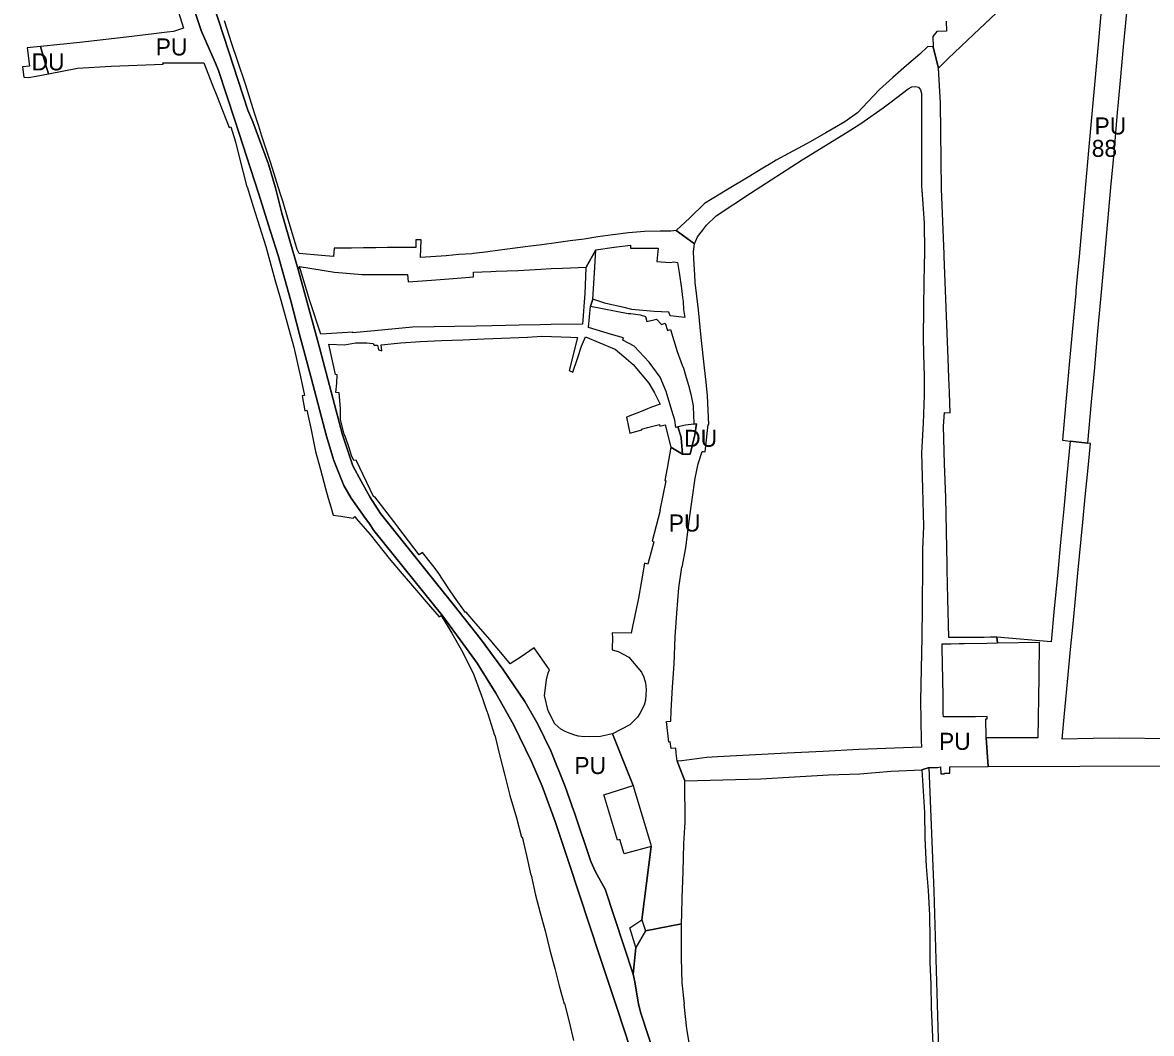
# Model space of a CAD drawing. Extents: x -521047 to -518054, y -1194945 to -1189555.
# Drawn here: x -520301 to -519638, y -1191621 to -1191028 of the extents above; entities that cross this region are included whole.
import ezdxf

# ---------------------------------------------------------------- set-up
doc = ezdxf.new("R2010")
doc.units = 0
for name, color, linetype in [('90310013', 7, 'Continuous'), ('90320013', 7, 'Continuous'), ('90450013', 7, 'Continuous'), ('90450023', 7, 'Continuous'), ('ID_navrh', 7, 'Continuous')]:
    doc.layers.add(name, color=color, linetype=linetype)

msp = doc.modelspace()

# ---------------------------------------------------------------- linework, layer by layer
at = {"layer": '90310013'}
for points in [[(-520290.15, -1191041.66), (-520297.9, -1191042.46), (-520296.62, -1191053.24), (-520300.69, -1191053.74), (-520299.9, -1191059.72), (-520297.2, -1191059.84), (-520292.62, -1191059.21), (-520285.55, -1191057.83), (-520287.18, -1191052.09), (-520290.15, -1191041.66)], [(-519916.16, -1191265), (-519914.43, -1191270.35), (-519914.24, -1191271.29), (-519913.38, -1191280.91), (-519908.95, -1191281.05), (-519906.08, -1191269.66), (-519905.16, -1191263.23), (-519906.65, -1191263.39), (-519911.61, -1191263.94), (-519916.16, -1191265)]]:
    msp.add_lwpolyline(points, dxfattribs=at)
at = {"layer": '90320013'}
for points in [[(-519929.33, -1191635.28), (-519937.84, -1191609.04), (-519939.31, -1191603.72), (-519941.34, -1191590.66), (-519942.38, -1191586.04), (-519958.85, -1191536.25), (-519964.41, -1191526.07), (-519967.28, -1191520.06), (-519976.95, -1191490.92), (-519977.14, -1191490.38), (-519982.28, -1191475.94), (-519990.75, -1191455.16), (-519998.32, -1191439.49), (-520005.92, -1191426.11), (-520018.78, -1191407.14), (-520031.96, -1191389.34), (-520047.36, -1191369.85), (-520056.18, -1191358.82), (-520087.5, -1191319.73), (-520090.59, -1191315.75), (-520096.97, -1191306.04), (-520102.06, -1191296.87), (-520106.82, -1191287.91), (-520108.84, -1191282.02), (-520112.91, -1191269.59), (-520126.29, -1191219.24), (-520128.27, -1191211.94), (-520139.04, -1191172.67), (-520142.39, -1191160.56), (-520148.63, -1191139.62), (-520152.18, -1191124.76), (-520156.39, -1191110.87), (-520165.49, -1191085.96), (-520168.55, -1191079.12), (-520182.63, -1191035.95), (-520230.16, -1190890.07)], [(-520204.26, -1191006.85), (-520195.92, -1191032.27), (-520192.65, -1191040.04), (-520187.45, -1191051.48), (-520185.72, -1191055.89), (-520176.15, -1191085.01), (-520162.23, -1191127.79), (-520155.09, -1191150.37), (-520150.78, -1191164.31), (-520143.35, -1191191.06), (-520138.27, -1191209.95), (-520131.25, -1191236.23), (-520122.24, -1191270.5), (-520118.08, -1191284.68), (-520112.12, -1191299.26), (-520107.85, -1191306.72), (-520099.92, -1191318.12), (-520097.08, -1191321.95), (-520094.55, -1191325.76), (-520054.11, -1191375.97), (-520040.12, -1191395.1), (-520033.82, -1191403.71), (-520022.9, -1191421.16), (-520012.56, -1191439.55), (-520001.92, -1191461.39), (-519995.8, -1191475.78), (-519988.12, -1191496.63), (-519987.95, -1191497.1), (-519979.96, -1191521.18), (-519962.02, -1191575.25), (-519951.7, -1191606.35), (-519940.4, -1191640.9)]]:
    msp.add_lwpolyline(points, dxfattribs=at)
at = {"layer": '90450013'}
for points in [[(-520230.16, -1190890.07), (-520182.63, -1191035.95), (-520168.55, -1191079.12), (-520165.49, -1191085.96), (-520156.39, -1191110.87), (-520152.18, -1191124.76), (-520148.63, -1191139.62), (-520142.39, -1191160.56), (-520139.04, -1191172.67), (-520138.13, -1191170.78), (-520117.56, -1191174.16), (-520101.36, -1191175.5), (-520098.41, -1191175.51), (-520085.69, -1191175.56), (-520074.77, -1191175.58), (-520074.38, -1191179.89), (-520060.7, -1191178.8), (-520048.06, -1191177.79), (-520035.98, -1191176.83), (-520036.11, -1191174.26), (-520025.87, -1191173.81), (-520022.83, -1191173.67), (-520009.79, -1191173.09), (-519996.61, -1191172.4), (-519990.39, -1191172.07), (-519983.74, -1191171.91), (-519970.02, -1191171.19), (-519964.25, -1191161.05), (-519953.43, -1191159.49), (-519943.95, -1191158.24), (-519943.98, -1191160.12), (-519935.85, -1191160.12), (-519927.72, -1191160.13), (-519928.53, -1191167.88), (-519920.55, -1191168.51), (-519918.44, -1191168.12), (-519916.29, -1191168.48), (-519915.26, -1191174.39), (-519913.96, -1191183.78), (-519913.39, -1191189.06), (-519913, -1191191.33), (-519912.75, -1191196.14), (-519912.03, -1191200.85), (-519920.68, -1191199.83), (-519921.43, -1191197.69), (-519929.98, -1191197.2), (-519943.03, -1191196), (-519947.61, -1191194.92), (-519958.38, -1191192.52), (-519966.04, -1191190.04), (-519967.41, -1191194.21), (-519945.24, -1191198.35), (-519943.8, -1191198.34), (-519938.16, -1191199.21), (-519935.07, -1191200.13), (-519934.36, -1191203.1), (-519928.62, -1191201.78), (-519925.65, -1191204.83), (-519923.55, -1191204.18), (-519922.15, -1191208.43), (-519920.47, -1191207.87), (-519916.57, -1191220.78), (-519913.59, -1191228.72), (-519912.89, -1191230.58), (-519911.2, -1191236.06), (-519909.81, -1191240.56), (-519908.47, -1191245.74), (-519907.22, -1191252.6), (-519906.89, -1191258.42), (-519906.67, -1191262.43), (-519906.65, -1191263.39), (-519905.16, -1191263.23), (-519906.08, -1191269.66), (-519908.95, -1191281.05), (-519913.38, -1191280.91), (-519920.21, -1191276.92), (-519922.38, -1191289.15), (-519923.7, -1191296.5), (-519923.11, -1191296.61), (-519926.79, -1191313.93), (-519926.46, -1191314.06), (-519931.24, -1191332.12), (-519930.12, -1191332.44), (-519933.8, -1191345.5), (-519935.76, -1191344.99), (-519937.5, -1191355.37), (-519939.28, -1191365.4), (-519942.75, -1191382.18), (-519943.6, -1191386.09), (-519954.59, -1191385.78), (-519954.39, -1191389.04), (-519954.6, -1191395.07), (-519954.76, -1191395.73), (-519951.1, -1191396.7), (-519944.83, -1191400.03), (-519937.5, -1191408.96), (-519936.08, -1191411.87), (-519935.13, -1191415.1), (-519934.72, -1191419.07), (-519935.15, -1191425.43), (-519935.94, -1191428.27), (-519938.47, -1191433.25), (-519939.86, -1191435.3), (-519944.28, -1191439.79), (-519954.39, -1191445.09), (-519942.41, -1191475.46), (-519941.97, -1191476.92), (-519932.24, -1191509.41), (-519931.7, -1191511.23), (-519937.21, -1191554.24), (-519935.12, -1191560.62), (-519913.95, -1191556.52), (-519913.95, -1191556.32), (-519913.77, -1191550.69), (-519913.55, -1191541.51), (-519913.02, -1191525.99), (-519912.6, -1191509.42), (-519912.08, -1191500.02), (-519911.87, -1191497.15), (-519912.09, -1191472.75), (-519916.57, -1191461.19), (-519917.06, -1191456.51), (-519917.37, -1191453.48), (-519920.04, -1191453.76), (-519920.61, -1191449.84), (-519921.5, -1191449.97), (-519922.75, -1191437.85), (-519920.31, -1191437.6), (-519920.06, -1191431.33)], [(-519940.4, -1191640.9), (-519951.7, -1191606.35), (-519962.02, -1191575.25), (-519979.96, -1191521.18), (-519987.95, -1191497.1), (-519988.12, -1191496.63), (-519995.8, -1191475.78), (-520001.92, -1191461.39), (-520012.56, -1191439.55), (-520022.9, -1191421.16), (-520033.82, -1191403.71), (-520040.12, -1191395.1), (-520054.11, -1191375.97), (-520094.55, -1191325.76), (-520097.08, -1191321.95), (-520099.92, -1191318.12), (-520107.85, -1191306.72), (-520112.12, -1191299.26), (-520118.08, -1191284.68), (-520122.24, -1191270.5), (-520131.25, -1191236.23), (-520138.27, -1191209.95), (-520143.35, -1191191.06), (-520150.78, -1191164.31), (-520155.09, -1191150.37), (-520162.23, -1191127.79), (-520176.15, -1191085.01), (-520185.72, -1191055.89), (-520187.45, -1191051.48), (-520192.65, -1191040.04), (-520195.92, -1191032.27), (-520204.26, -1191006.85)], [(-520210.43, -1191017.92), (-520206.21, -1191031.01), (-520212.09, -1191033), (-520215.8, -1191033.39), (-520222.04, -1191034.03), (-520236.52, -1191035.95), (-520267.13, -1191039.3), (-520290.15, -1191041.66)], [(-519758.73, -1191026.94), (-519758.39, -1191032.67), (-519764.15, -1191032.99), (-519766.57, -1191035.82), (-519766.2, -1191042.12), (-519763.15, -1191054.45), (-519757.4, -1191048.8), (-519742.58, -1191034.77), (-519725.84, -1191018.93)], [(-519920.06, -1191431.33), (-519919.21, -1191417.69), (-519918.28, -1191404.11), (-519917.62, -1191388.13), (-519916.71, -1191374.33), (-519915.54, -1191359.47), (-519913.79, -1191347.3), (-519913.62, -1191347.33), (-519911.48, -1191335.89), (-519909.39, -1191320.12), (-519905.88, -1191295.06), (-519904.2, -1191286.61), (-519901.8, -1191279.37), (-519901.12, -1191279.43), (-519900.01, -1191279.6), (-519898.29, -1191263.61), (-519897.85, -1191263.62), (-519898.78, -1191246.64), (-519899.59, -1191238.79), (-519900.46, -1191230.4), (-519902.53, -1191212.53), (-519904.01, -1191196.27), (-519905.9, -1191180.16), (-519906.15, -1191175.73), (-519906.66, -1191166.6), (-519906.92, -1191162.01), (-519906.3, -1191157.45), (-519917.19, -1191149.74), (-519920.32, -1191150.09), (-519926.43, -1191150.12), (-519935.74, -1191150.21), (-519945.04, -1191151.11), (-519954.19, -1191152.2), (-519963.01, -1191153.4), (-519971.18, -1191154.8), (-519979.27, -1191155.87), (-519987.57, -1191156.97), (-519995.89, -1191158.07), (-520004.25, -1191159.18), (-520020.52, -1191161.34), (-520029.05, -1191162.47), (-520035.97, -1191163.26), (-520036.96, -1191163.37), (-520044.63, -1191163.89), (-520052.03, -1191164.58), (-520067.15, -1191165.61), (-520066.74, -1191155.17), (-520069.93, -1191155.16), (-520069.95, -1191159.63), (-520079.48, -1191159.67), (-520086.45, -1191159.75), (-520093.39, -1191159.83), (-520100.51, -1191159.91), (-520107.64, -1191159.99), (-520117.85, -1191160.11), (-520118.2, -1191164.94), (-520125.16, -1191164.31), (-520138.44, -1191163.28), (-520139.59, -1191160.92), (-520145.2, -1191141.87), (-520147.8, -1191133.04), (-520149.55, -1191127.71), (-520154.98, -1191110.13), (-520160.34, -1191094.39), (-520162.03, -1191088.51), (-520164.64, -1191080.79), (-520169.68, -1191064.45), (-520174.58, -1191049.98), (-520177.92, -1191040.13), (-520182.12, -1191026.63)], [(-520290.15, -1191041.66), (-520287.18, -1191052.09), (-520285.55, -1191057.83), (-520268.52, -1191054.51), (-520248.67, -1191053.28), (-520218.2, -1191052.16), (-520218.34, -1191051.28), (-520194.34, -1191051.32), (-520193.93, -1191052.35), (-520189.56, -1191063.43), (-520186.26, -1191071.67), (-520182.97, -1191080.18), (-520179.53, -1191089.2), (-520178.54, -1191088.91), (-520175.78, -1191097.65), (-520173.5, -1191106.5), (-520169.07, -1191124.06), (-520168.8, -1191124), (-520165.31, -1191135.53), (-520161.55, -1191147.43), (-520157.86, -1191159.19), (-520152.57, -1191178.38), (-520149.52, -1191189.15), (-520147.14, -1191197.72), (-520144.34, -1191207.7), (-520141.5, -1191218.1), (-520137.26, -1191237.41), (-520135.23, -1191246.57), (-520136.61, -1191246.77), (-520135.11, -1191255.48), (-520133.8, -1191255.22), (-520131.57, -1191265.71), (-520128.76, -1191279.31), (-520125.9, -1191289.88), (-520122.99, -1191301.11), (-520121.28, -1191306.84), (-520119.8, -1191311.78), (-520118.33, -1191316.72), (-520113.9, -1191317.42), (-520106.74, -1191318.55), (-520105.72, -1191317.64), (-520104.86, -1191318.64), (-520096.75, -1191328.08), (-520085.55, -1191342.11), (-520077.83, -1191351.1), (-520070.7, -1191359.65), (-520063.86, -1191367.71), (-520056.23, -1191376.45), (-520055.09, -1191375.72), (-520048.83, -1191385.95), (-520043.17, -1191395.94), (-520039.57, -1191402.87), (-520035.85, -1191410.48), (-520030.86, -1191424.4), (-520028.75, -1191430.16), (-520027.59, -1191433.32), (-520023.82, -1191445.95), (-520023.55, -1191445.91), (-520020.73, -1191457.45), (-520017.66, -1191469.57), (-520014.7, -1191481.23), (-520010.89, -1191494.47), (-520010.73, -1191494.41), (-520007.79, -1191505.69), (-520007.55, -1191505.56), (-520004.99, -1191516.5), (-520002.46, -1191528.07), (-520002.17, -1191528.01), (-519999.67, -1191539.74), (-519997.02, -1191550.13), (-519996.86, -1191550.12), (-519994.03, -1191560.71), (-519991.17, -1191572.07), (-519988.4, -1191582.72), (-519985.82, -1191593.01), (-519982.81, -1191603.46), (-519982.61, -1191603.4), (-519979.91, -1191614.16), (-519977.29, -1191625.06)], [(-519756.23, -1191256.68), (-519756.69, -1191244.83), (-519757.02, -1191236.26), (-519757.46, -1191224.85), (-519758.24, -1191204.87), (-519759.79, -1191165), (-519759.85, -1191163.64), (-519761.34, -1191125.25), (-519762.07, -1191075.06), (-519763.15, -1191054.45), (-519766.2, -1191042.12), (-519766.5, -1191042.12), (-519766.53, -1191041.7), (-519769.56, -1191041.92), (-519774.17, -1191046.21), (-519781.93, -1191052.87), (-519789.9, -1191059.99), (-519797.75, -1191067), (-519804.69, -1191074.24), (-519810.75, -1191080.57), (-519818.12, -1191085.97), (-519829.31, -1191092.4), (-519838.45, -1191097.64), (-519840.61, -1191098.81), (-519851.15, -1191104.5), (-519858.51, -1191108.47), (-519862.58, -1191110.94), (-519866.19, -1191113.13), (-519874.86, -1191118.39), (-519886.98, -1191125.74), (-519900.42, -1191133.89), (-519909.06, -1191142.26), (-519917.19, -1191149.74), (-519906.3, -1191157.45), (-519904.56, -1191153.47), (-519901.59, -1191149.65), (-519899.24, -1191146.62), (-519893.57, -1191141.01), (-519873.58, -1191127.87), (-519843.17, -1191108.24), (-519816.71, -1191092.03), (-519808.76, -1191086.91), (-519795.57, -1191077.78), (-519790.92, -1191074.25), (-519780.88, -1191066.51), (-519778.77, -1191065.35), (-519776.49, -1191065.19), (-519774.92, -1191065.69), (-519773.63, -1191067.16), (-519773.09, -1191069.29), (-519773.08, -1191073.94), (-519773.05, -1191092.19), (-519773.06, -1191101.44), (-519773.1, -1191123.95), (-519772.97, -1191125.9), (-519771.62, -1191145.39), (-519771.43, -1191162.03), (-519771.76, -1191179.56), (-519771.96, -1191195.31), (-519772.12, -1191213.02), (-519771.84, -1191229.67), (-519771.55, -1191234.29), (-519771.54, -1191246.41), (-519772.05, -1191262.81), (-519773.13, -1191280.12), (-519772.53, -1191301.2), (-519772, -1191323.45), (-519772.56, -1191336.73), (-519772.53, -1191348.9), (-519772.74, -1191367.61), (-519772.78, -1191370.92), (-519772.98, -1191388.27), (-519773.78, -1191425.6), (-519773.27, -1191448.99), (-519773.21, -1191452.93), (-519809.91, -1191454.37), (-519830.9, -1191455.42), (-519851.93, -1191456.47), (-519892.88, -1191458.5), (-519899.19, -1191459.03), (-519913.72, -1191460.84), (-519916.57, -1191461.19), (-519912.09, -1191472.75), (-519867.51, -1191471.49), (-519847.68, -1191470.41), (-519827.66, -1191469.23), (-519809.38, -1191468.51), (-519791.02, -1191466.98), (-519772.94, -1191466.17), (-519768.59, -1191464.89), (-519763.77, -1191464.94), (-519761.94, -1191464.39), (-519761.87, -1191468.64), (-519759.57, -1191468.66), (-519759.58, -1191468.17), (-519756.5, -1191468.24), (-519756.52, -1191464.38), (-519734.08, -1191464.3), (-519735.24, -1191447.53), (-519735.35, -1191436.29), (-519734.64, -1191436.32), (-519734.65, -1191434.99), (-519741.34, -1191435.03), (-519750.83, -1191435.08), (-519760.31, -1191435.14), (-519760.35, -1191433.14), (-519760.41, -1191429.18), (-519760.5, -1191422.78), (-519760.92, -1191394.34), (-519760.94, -1191392.31), (-519760.93, -1191392.31), (-519755.94, -1191392.22), (-519750.95, -1191392.13), (-519748.1, -1191392.08), (-519734.6, -1191391.84), (-519728.58, -1191391.74), (-519728.83, -1191388.41), (-519732.63, -1191388.44), (-519736.35, -1191388.47), (-519757.13, -1191388.64), (-519757.61, -1191365.82), (-519757.97, -1191348.75), (-519758.03, -1191345.99), (-519758.44, -1191326.19), (-519758.86, -1191306.37), (-519759.53, -1191286.62), (-519760.31, -1191264.48), (-519759.7, -1191256.5), (-519756.23, -1191256.68)], [(-519977.75, -1191232.89), (-519975.09, -1191224.78), (-519972.7, -1191217.51), (-519970.38, -1191212.1), (-519953.47, -1191219.12), (-519952.81, -1191219.41), (-519947.91, -1191223.59), (-519942.39, -1191228.3), (-519933.11, -1191239.36), (-519929.76, -1191245.02), (-519926.51, -1191251.7), (-519931.68, -1191253.32), (-519935.33, -1191254.97), (-519939.55, -1191256.63), (-519942.81, -1191257.91), (-519946.16, -1191259.22), (-519944.27, -1191268.71), (-519937.27, -1191266.67), (-519937.35, -1191266.3), (-519933.91, -1191265.26), (-519926.88, -1191263.59), (-519926.61, -1191264.58), (-519923.57, -1191263.81), (-519920.21, -1191276.92), (-519913.38, -1191280.91), (-519914.24, -1191271.29), (-519914.43, -1191270.35), (-519916.16, -1191265), (-519917.33, -1191265.27), (-519917.97, -1191260.92), (-519919.56, -1191255.43), (-519922.97, -1191244.2), (-519926.57, -1191235.7), (-519932.99, -1191226.94), (-519941.84, -1191217.63), (-519948.33, -1191214.01), (-519947.97, -1191212.68), (-519955.03, -1191210.72), (-519968.52, -1191206.69), (-519967.41, -1191194.21), (-519966.04, -1191190.04), (-519965.08, -1191174.59), (-519964.25, -1191161.05), (-519970.02, -1191171.19), (-519970.04, -1191171.59), (-519970.65, -1191186.76), (-519972.15, -1191204.62), (-519990.46, -1191204.97), (-519996.86, -1191205.09), (-520009.2, -1191205.33), (-520025.3, -1191205.64), (-520034.44, -1191205.82), (-520046.93, -1191206.05), (-520059.07, -1191206.28), (-520071.84, -1191206.53), (-520094.07, -1191208.67), (-520106.88, -1191209.86), (-520106.94, -1191209.29), (-520125.69, -1191210.45), (-520132.06, -1191191), (-520138.13, -1191170.78), (-520139.04, -1191172.67), (-520128.27, -1191211.94), (-520126.29, -1191219.24), (-520112.91, -1191269.59), (-520108.84, -1191282.02), (-520106.82, -1191287.91), (-520102.06, -1191296.87), (-520096.97, -1191306.04), (-520090.59, -1191315.75), (-520087.5, -1191319.73), (-520056.18, -1191358.82), (-520047.36, -1191369.85), (-520031.96, -1191389.34), (-520018.78, -1191407.14), (-520005.92, -1191426.11), (-519998.32, -1191439.49), (-519990.75, -1191455.16), (-519982.28, -1191475.94), (-519977.14, -1191490.38), (-519976.95, -1191490.92), (-519967.28, -1191520.06), (-519964.41, -1191526.07), (-519958.85, -1191536.25), (-519942.38, -1191586.04), (-519940.69, -1191570.43), (-519941.33, -1191568.45), (-519944.39, -1191558.98), (-519937.21, -1191554.24), (-519931.7, -1191511.23), (-519947.58, -1191515.44), (-519950.26, -1191507.13), (-519951.55, -1191507.52), (-519959.23, -1191482.01), (-519959.57, -1191480.86), (-519942.41, -1191475.46), (-519954.39, -1191445.09), (-519961.53, -1191446.75), (-519971.13, -1191446.91), (-519974.5, -1191446.39), (-519976.56, -1191445.88), (-519979.32, -1191444.93), (-519982.27, -1191443.78), (-519984.74, -1191442.4), (-519988.3, -1191439.28), (-519992.15, -1191431.52), (-519994.38, -1191422.52), (-519993.24, -1191413.37), (-519992.22, -1191409.33), (-519991.42, -1191407.59), (-520000.38, -1191394.59), (-520008.16, -1191399.97), (-520014.57, -1191404), (-520016.12, -1191402.07), (-520026.28, -1191389.97), (-520034.63, -1191380.32), (-520040.42, -1191373.62), (-520040.73, -1191373.84), (-520047.19, -1191364.83), (-520050.47, -1191359.95), (-520056.7, -1191350.51), (-520059.94, -1191346.32), (-520065.92, -1191338.59), (-520067.95, -1191340.12), (-520077.35, -1191327.73), (-520082.89, -1191320.43), (-520093.9, -1191305.93), (-520094.5, -1191306.24), (-520104.98, -1191284.57), (-520106.3, -1191284.7), (-520107.61, -1191281.7), (-520108.9, -1191277.92), (-520111.26, -1191271), (-520111.87, -1191269.22), (-520114.16, -1191260.56), (-520114.12, -1191254.11), (-520114.83, -1191244.91), (-520116.83, -1191244.69), (-520116.22, -1191239.35), (-520116.09, -1191234.37), (-520116.97, -1191234.24), (-520121.04, -1191216.51), (-520111.74, -1191216.83), (-520105.33, -1191215.65), (-520098.62, -1191215.71), (-520095.07, -1191216.04), (-520094.3, -1191217.09), (-520092.4, -1191216.95), (-520091.83, -1191219.76), (-520089.85, -1191220.37), (-520090.21, -1191216.78), (-520078.64, -1191215.7), (-520067.14, -1191214.8), (-520054.83, -1191214.31), (-520042.28, -1191213.81), (-520029.73, -1191213.31), (-520004.4, -1191212.3), (-519996.02, -1191211.66), (-519978.9, -1191212.24), (-519975.11, -1191212.49), (-519979.96, -1191231.95), (-519977.75, -1191232.89)], [(-519627.09, -1191448.06), (-519657.04, -1191447.59), (-519672.39, -1191447.84), (-519690.58, -1191448.2), (-519689.15, -1191433.2), (-519686.98, -1191410.48), (-519685.63, -1191395.51), (-519684.19, -1191380.58), (-519682.82, -1191365.8), (-519681.41, -1191350.72), (-519678.45, -1191320.85), (-519677.01, -1191305.92), (-519675.58, -1191290.99), (-519673.88, -1191274.66), (-519675.47, -1191274.48), (-519685.82, -1191273.28), (-519687.75, -1191293.42), (-519689.63, -1191313.08), (-519691.5, -1191332.59), (-519693.37, -1191352.18), (-519695.23, -1191371.61), (-519697.1, -1191391.12), (-519728.83, -1191388.41), (-519728.58, -1191391.74), (-519704.02, -1191391.33), (-519704.32, -1191411.74), (-519704.85, -1191447.45), (-519714.19, -1191447.43), (-519735.24, -1191447.53), (-519734.08, -1191464.3), (-519626.5, -1191463.94)], [(-519762.65, -1191643.76), (-519765.6, -1191537.51), (-519768.59, -1191464.89), (-519772.94, -1191466.17), (-519771.36, -1191491.2), (-519771.22, -1191506.39), (-519770.37, -1191522.95), (-519769.16, -1191537.06), (-519768.42, -1191551.42), (-519768.27, -1191565.34), (-519768.14, -1191579.11), (-519767.74, -1191592.2), (-519767.43, -1191605.54), (-519766.89, -1191618.67), (-519766.35, -1191631.77)], [(-519908.85, -1191629.77), (-519910.89, -1191618.15), (-519912.42, -1191603.76), (-519912.21, -1191603.75), (-519913.59, -1191591.23), (-519914.06, -1191576.8), (-519914.02, -1191568.1), (-519913.95, -1191556.72), (-519913.95, -1191556.52), (-519935.12, -1191560.62), (-519940.69, -1191570.43), (-519942.38, -1191586.04), (-519941.34, -1191590.66), (-519939.31, -1191603.72), (-519937.84, -1191609.04), (-519929.33, -1191635.28)]]:
    msp.add_lwpolyline(points, dxfattribs=at)
at = {"layer": '90450023'}
for points in [[(-519667.64, -1191020.37), (-519669.45, -1191040.49), (-519671.21, -1191060), (-519673.12, -1191081.21), (-519675.06, -1191102.74), (-519676.87, -1191122.79), (-519678.66, -1191142.72), (-519680.66, -1191164.96), (-519681.35, -1191172.59), (-519682.46, -1191184.87), (-519682.61, -1191186.53), (-519684.47, -1191207.19), (-519686.37, -1191228.29), (-519688.16, -1191248.13), (-519690.37, -1191272.75), (-519685.82, -1191273.28), (-519675.47, -1191274.48)], [(-519675.47, -1191274.48), (-519673.28, -1191250.17), (-519671.47, -1191230.02), (-519669.56, -1191208.87), (-519667.69, -1191188.06), (-519665.75, -1191166.57), (-519663.75, -1191144.4), (-519661.95, -1191124.38), (-519660.14, -1191104.26), (-519658.21, -1191082.84), (-519656.29, -1191061.59), (-519654.53, -1191041.95), (-519652.71, -1191021.78)]]:
    msp.add_lwpolyline(points, dxfattribs=at)

# ---------------------------------------------------------------- texts
at = {"layer": '90310013'}
for p in [(-520295.38, -1191055.75), (-519912.41, -1191276.65)]:
    msp.add_text('DU', height=10, rotation=0, dxfattribs=at).set_placement(p)
at = {"layer": '90450013'}
for rotation, p in [(360, (-520222.54, -1191047)), (360, (-519921.43, -1191326.37)), (0, (-519762.84, -1191454.49)), (0, (-519976.84, -1191468.69))]:
    msp.add_text('PU', height=10, rotation=rotation, dxfattribs=at).set_placement(p)
at = {"layer": '90450023'}
msp.add_text('PU', height=10, rotation=0, dxfattribs=at).set_placement((-519671.56, -1191093.37))
at = {"layer": 'ID_navrh'}
msp.add_text('88', height=10, rotation=360, dxfattribs=at).set_placement((-519673.21, -1191106.53))

doc.saveas('drawing.dxf')
